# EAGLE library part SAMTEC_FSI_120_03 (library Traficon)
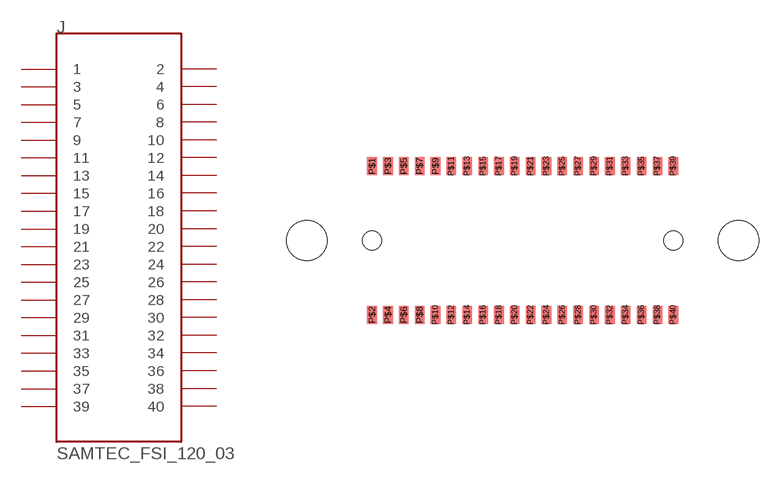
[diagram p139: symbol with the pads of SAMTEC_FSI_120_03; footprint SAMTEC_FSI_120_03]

Designator prefix J

## SAMTEC_FSI_120_03  [SAMTEC_FSI_120_03]
P$1  1
P$2  2
P$3  3
P$4  4
P$5  5
P$6  6
P$7  7
P$8  8
P$9  9
P$10  10
P$11  11
P$12  12
P$13  13
P$14  14
P$15  15
P$16  16
P$17  17
P$18  18
P$19  19
P$20  20
P$21  21
P$22  22
P$23  23
P$24  24
P$25  25
P$26  26
P$27  27
P$28  28
P$29  29
P$30  30
P$31  31
P$32  32
P$33  33
P$34  34
P$35  35
P$36  36
P$37  37
P$38  38
P$39  39
P$40  40

## Footprint SAMTEC_FSI_120_03 (pad centres in mm)
smd 0.61 x 1.13: P$1 -9.5,4.695; P$2 -9.5,-4.695; P$3 -8.5,4.695; P$4 -8.5,-4.695; P$5 -7.5,4.695; P$6 -7.5,-4.695; P$7 -6.5,4.695; P$8 -6.5,-4.695; P$9 -5.5,4.695; P$10 -5.5,-4.695; P$11 -4.5,4.695; P$12 -4.5,-4.695; P$13 -3.5,4.695; P$14 -3.5,-4.695; P$15 -2.5,4.695; P$16 -2.5,-4.695; P$17 -1.5,4.695; P$18 -1.5,-4.695; P$19 -0.5,4.695; P$20 -0.5,-4.695; P$21 0.5,4.695; P$22 0.5,-4.695; P$23 1.5,4.695; P$24 1.5,-4.695; P$25 2.5,4.695; P$26 2.5,-4.695; P$27 3.5,4.695; P$28 3.5,-4.695; P$29 4.5,4.695; P$30 4.5,-4.695; P$31 5.5,4.695; P$32 5.5,-4.695; P$33 6.5,4.695; P$34 6.5,-4.695; P$35 7.5,4.695; P$36 7.5,-4.695; P$37 8.5,4.695; P$38 8.5,-4.695; P$39 9.5,4.695; P$40 9.5,-4.695
hole 2.54 at -13.62,0
hole 2.54 at 13.62,0
hole 1.19 at -9.5,0
hole 1.19 at 9.5,0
